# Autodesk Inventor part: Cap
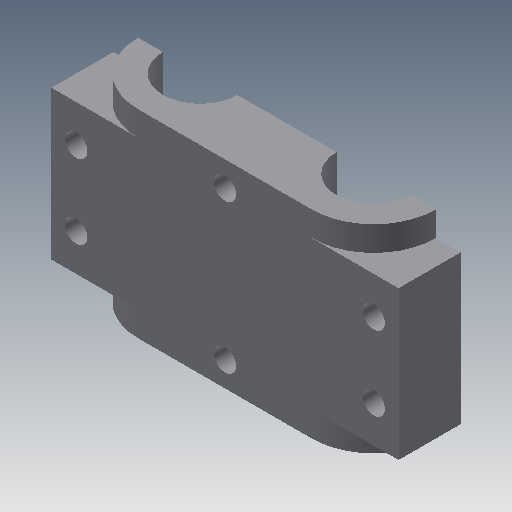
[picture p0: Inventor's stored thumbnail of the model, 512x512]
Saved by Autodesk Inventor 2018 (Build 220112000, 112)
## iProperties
Shininess: 77.0
Length Units: 11269
Angle Units: 11279
Time Units: 11290
Mass Units: 11283
Length Display Precision: 3
Angle Display Precision: 2
Created: 2002-02
Part Number: Cap
Document SubType Name: Modeling
Designer: ***
Density: 1 g/cm^3
Material: Generic
Appearance: Default
Density: 0.0
Volumn: 0.0
Area: 0.0
PropertySet Name: Model Information
Control State: 0
Master: False
Checked Out: False
Author: ***
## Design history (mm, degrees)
sketch "Sketch2"
  geometry: L1 (-17.5, 12.5)-(17.5, 12.5); L2 (30, 0)-(25, 0); L3 (10, 0)-(-10, 0); L4 (-25, 0)-(-30, 0); A1 r 12.5 centre (-17.5, 0) between (-17.5, 12.5) and (-30, 0); A2 r 12.5 centre (17.5, 0) between (30, 0) and (17.5, 12.5); A3 r 7.5 centre (17.5, 0) between (25, 0) and (10, 0); A4 r 7.5 centre (-17.5, 0) between (-10, 0) and (-25, 0)
  constraints: 8 end point, 8 point on circle, 4 centre point, 3 horizontal, 3 parallel, 2 coincident, 2 equal radius, 2 tangent
  dimensions: "d0" = 12.5 radius of A1; "d1" = 7.5 radius of A4; "d2" = 35 distance of A1.centre A2.centre; "d3" = 12.5 distance between parallel lines of L1 L3
extrude "Extrusion1" new body sketch "Sketch2" stored distance "d4" = 40; taper "d5" = 0 deg
workplane "Work Plane1"
sketch "Sketch3"
  geometry: L1 (-15, 12.5)-(15, 12.5); L2 (15, 12.5)-(15, 0); L3 (15, 0)-(-15, 0); L4 (-15, 0)-(-15, 12.5); L5 (-20, 0)-(20, 0) reference; L6 (-20, 12.5)-(20, 12.5) reference; L7 (20, 12.5)-(20, 0) reference
  constraints: 8 end point, 2 collinear, 2 parallel, 1 horizontal, 1 perpendicular
  dimensions: "d7" = 30 distance of L2.end L3.end; "d8" = 5 distance between parallel lines of L7 L2
extrude "Extrusion2" join sketch "Sketch3" stored distance "d9" = 40; taper "d10" = 0 deg
mirror "Mirror1"
sketch "Sketch4"
  geometry: L1 (-17.5, -35)-(0, -35) reference; L2 (-17.5, -35)-(-17.5, -5) reference; 1 further point
  dimensions: "d12" = 7.5 distance from line of L1 point (-12.5, -27.5); "d13" = 5 distance from line of L2 point (-12.5, -27.5)
hole "Hole1" sketch "Sketch4" at (-12.5, -27.5) diameter "d14" = 4.5; stored, may be unused: countersink angle "d18" = 82 deg, drill point angle "d20" = 118 deg; dims "d15" = 6, "d16" = 4, "d17" = 2, "d19" = 8
pattern_linear "Rectangular Pattern1" dims "d23" = 60, "d26" = 15
sketch "Sketch5"
  geometry: L1 (0, -40)-(35, -40) reference; L2 (-17.5, -35)-(-17.5, -5) reference; 1 further point
  dimensions: "d27" = 5 distance from line of L1 point (17.5, -35); "d28" = 35 distance from line of L2 point (17.5, -35)
hole "Hole2" sketch "Sketch5" at (17.5, -35) diameter "d29" = 4.5; stored, may be unused: countersink angle "d33" = 82 deg, drill point angle "d35" = 118 deg; dims "d30" = 6, "d31" = 4, "d32" = 2, "d34" = 8
pattern_linear "Rectangular Pattern2" dims "d38" = 30
body "Solid1"
other parameters: "d11" = 35
